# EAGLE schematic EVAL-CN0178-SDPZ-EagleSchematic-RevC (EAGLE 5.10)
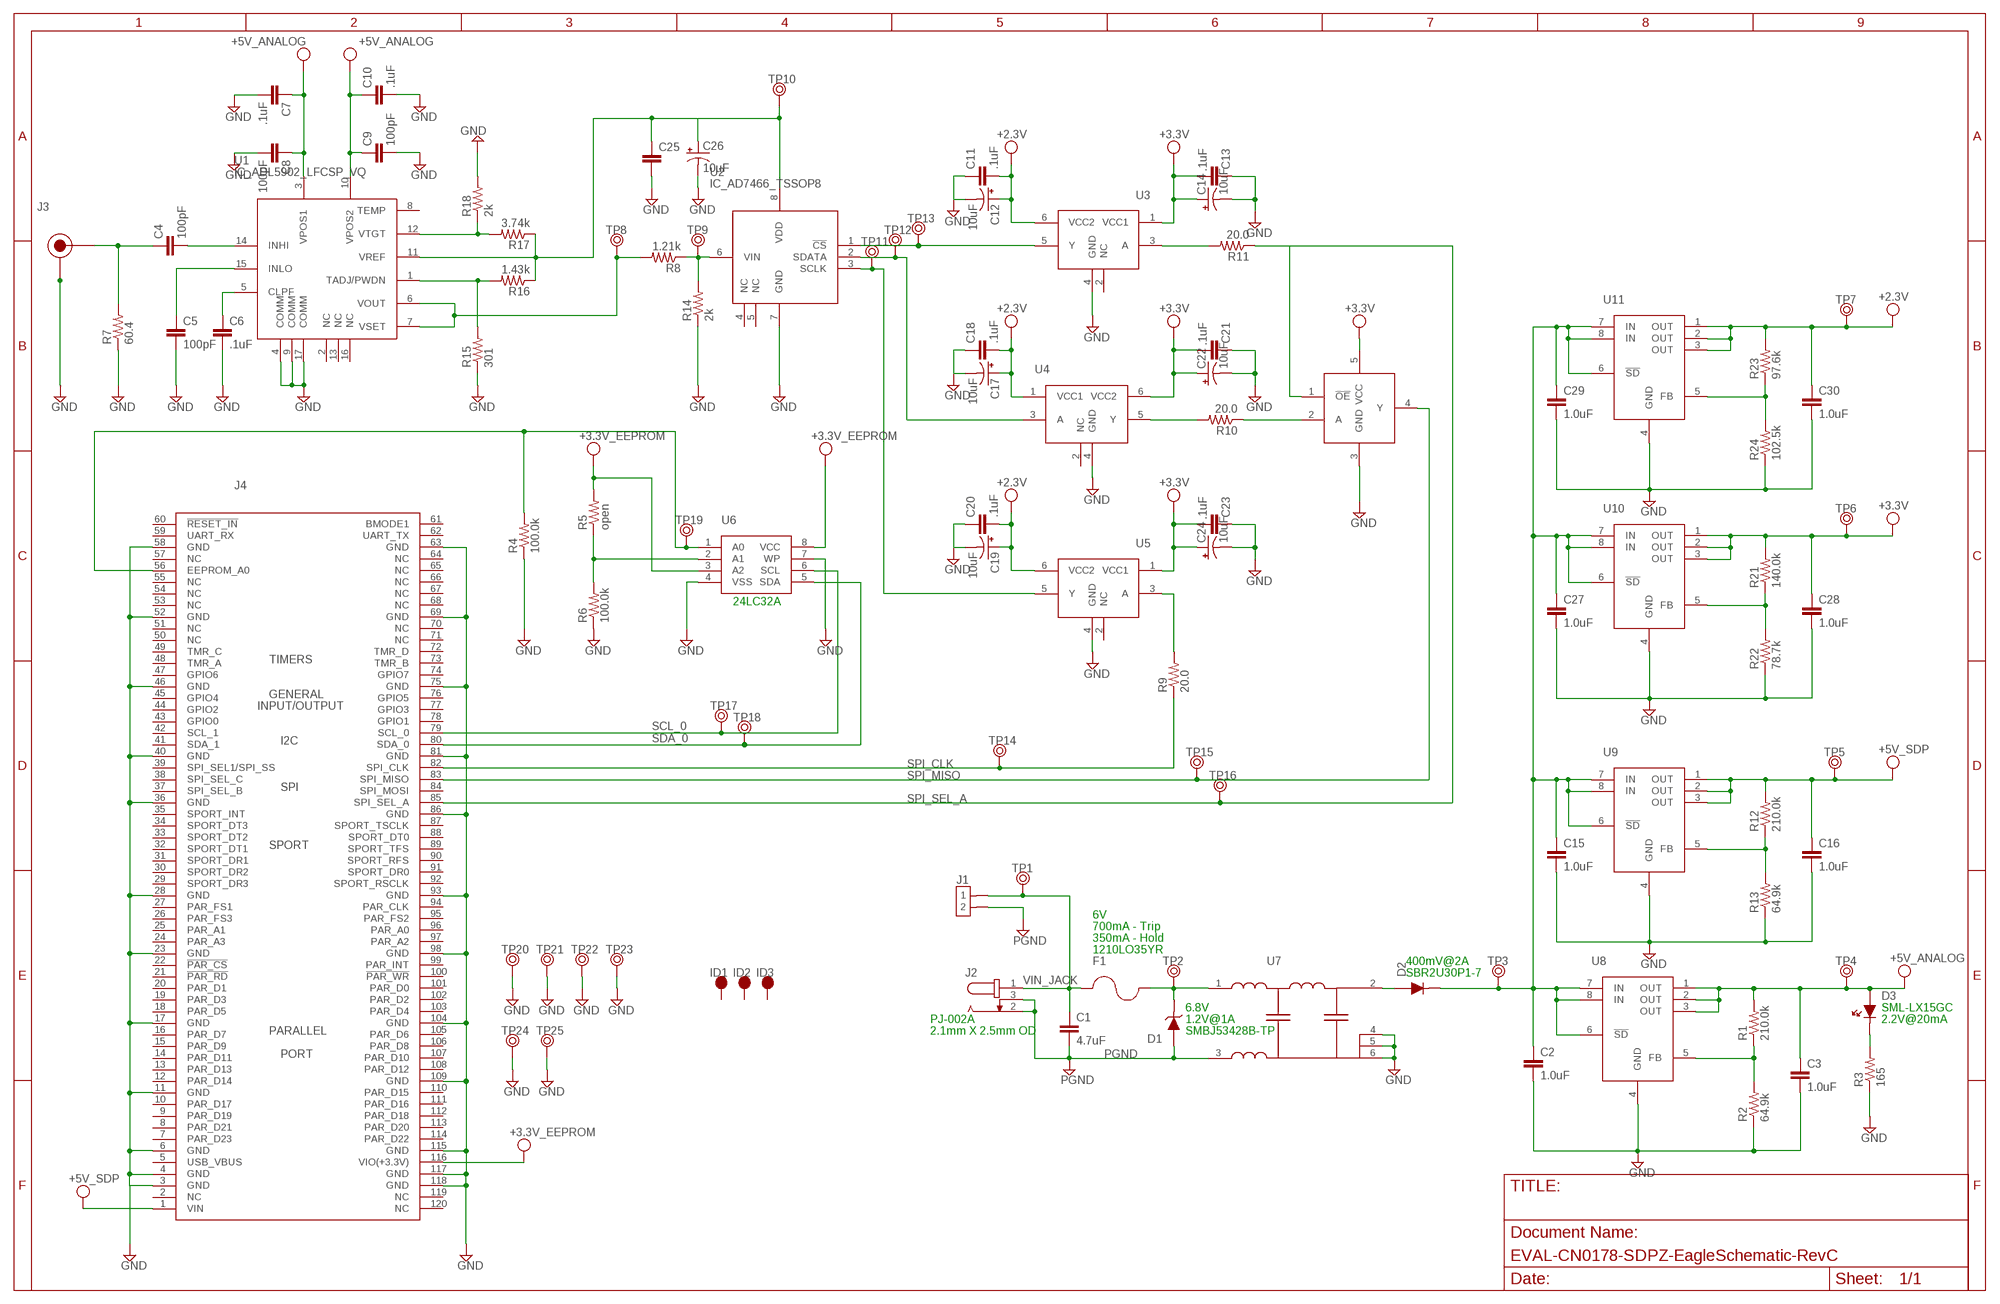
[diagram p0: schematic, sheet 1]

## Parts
C1  4.7uF  CAPACITOR_0603  [C_CAPC1608X55N]
C2  1.0uF  CAPACITOR_0603  [C_CAPC1608X55N]
C3  1.0uF  CAPACITOR_0603  [C_CAPC1608X55N]
C4  100pF  CAPACITOR_0402  [C_CAPC1005X55N]
C5  100pF  CAPACITOR_0402  [C_CAPC1005X55N]
C6  .1uF  CAPACITOR_0402  [C_CAPC1005X55N]
C7  .1uF  CAPACITOR_0402  [C_CAPC1005X55N]
C8  100pF  CAPACITOR_0402  [C_CAPC1005X55N]
C9  100pF  CAPACITOR_0402  [C_CAPC1005X55N]
C10  .1uF  CAPACITOR_0402  [C_CAPC1005X55N]
C11  .1uF  CAPACITOR_0603  [C_CAPC1608X55N]
C12  10uF  CAPACITOR_POL_3216-18  [C_CAPMP3216X180N]
C13  .1uF  CAPACITOR_0603  [C_CAPC1608X55N]
C14  10uF  CAPACITOR_POL_3216-18  [C_CAPMP3216X180N]
C15  1.0uF  CAPACITOR_0603  [C_CAPC1608X55N]
C16  1.0uF  CAPACITOR_0603  [C_CAPC1608X55N]
C17  10uF  CAPACITOR_POL_3216-18  [C_CAPMP3216X180N]
C18  .1uF  CAPACITOR_0603  [C_CAPC1608X55N]
C19  10uF  CAPACITOR_POL_3216-18  [C_CAPMP3216X180N]
C20  .1uF  CAPACITOR_0603  [C_CAPC1608X55N]
C21  .1uF  CAPACITOR_0603  [C_CAPC1608X55N]
C22  10uF  CAPACITOR_POL_3216-18  [C_CAPMP3216X180N]
C23  .1uF  CAPACITOR_0603  [C_CAPC1608X55N]
C24  10uF  CAPACITOR_POL_3216-18  [C_CAPMP3216X180N]
C25  CAPACITOR_0603  [C_CAPC1608X55N]
C26  10uF  CAPACITOR_POL_3216-18  [C_CAPMP3216X180N]
C27  1.0uF  CAPACITOR_0603  [C_CAPC1608X55N]
C28  1.0uF  CAPACITOR_0603  [C_CAPC1608X55N]
C29  1.0uF  CAPACITOR_0603  [C_CAPC1608X55N]
C30  1.0uF  CAPACITOR_0603  [C_CAPC1608X55N]
D1  DIODE_ZENER_DO-214AA,SMB  [D_DIOM5436X241N]
D2  DIODE_RECT_POWERDI-123  [D_POWER123]
D3  DIODE_LED_SOT_23-3  [D_LED_LUMEX_SMD]
F1  FUSE_1210  [C_CAPC3225X94N]
ID1  INDICATOR  [ID_PICKNPLACE]
ID2  INDICATOR  [ID_PICKNPLACE]
ID3  INDICATOR  [ID_PICKNPLACE]
J1  CON_HEADER_2PIN  [CON_HEADER_2PIN]
J2  CON_DC_BARREL_THRU_HOLE  [CON_BARREL_JACK]
J3  CON_COAX_SMD  [CON_COAX_SMD]
J4  CON_SDP_120PIN_SMD  [CON_120PIN_SMD]
R1  210.0k  RESISTOR_0603  [R_RESC1608X50AN]
R2  64.9k  RESISTOR_0603  [R_RESC1608X50AN]
R3  165  RESISTOR_0603  [R_RESC1608X50AN]
R4  100.0k  RESISTOR_0603  [R_RESC1608X50AN]
R5  open  RESISTOR_0603  [R_RESC1608X50AN]
R6  100.0k  RESISTOR_0603  [R_RESC1608X50AN]
R7  60.4  RESISTOR_0402_RF  [R_RESC1005X40N_RF]
R8  1.21k  RESISTOR_0603  [R_RESC1608X50AN]
R9  20.0  RESISTOR_0603  [R_RESC1608X50AN]
R10  20.0  RESISTOR_0603  [R_RESC1608X50AN]
R11  20.0  RESISTOR_0603  [R_RESC1608X50AN]
R12  210.0k  RESISTOR_0603  [R_RESC1608X50AN]
R13  64.9k  RESISTOR_0603  [R_RESC1608X50AN]
R14  2k  RESISTOR_0603  [R_RESC1608X50AN]
R15  301  RESISTOR_0603  [R_RESC1608X50AN]
R16  1.43k  RESISTOR_0603  [R_RESC1608X50AN]
R17  3.74k  RESISTOR_0603  [R_RESC1608X50AN]
R18  2k  RESISTOR_0603  [R_RESC1608X50AN]
R21  140.0k  RESISTOR_0603  [R_RESC1608X50AN]
R22  78.7k  RESISTOR_0603  [R_RESC1608X50AN]
R23  97.6k  RESISTOR_0603  [R_RESC1608X50AN]
R24  102.5k  RESISTOR_0603  [R_RESC1608X50AN]
TP1  TESTPOINT_50MIL  [TP_50MIL]
TP2  TESTPOINT_50MIL  [TP_50MIL]
TP3  TESTPOINT_50MIL  [TP_50MIL]
TP4  TESTPOINT_50MIL  [TP_50MIL]
TP5  TESTPOINT_50MIL  [TP_50MIL]
TP6  TESTPOINT_50MIL  [TP_50MIL]
TP7  TESTPOINT_50MIL  [TP_50MIL]
TP8  TESTPOINT_50MIL  [TP_50MIL]
TP9  TESTPOINT_50MIL  [TP_50MIL]
TP10  TESTPOINT_50MIL  [TP_50MIL]
TP11  TESTPOINT_50MIL  [TP_50MIL]
TP12  TESTPOINT_50MIL  [TP_50MIL]
TP13  TESTPOINT_50MIL  [TP_50MIL]
TP14  TESTPOINT_50MIL  [TP_50MIL]
TP15  TESTPOINT_50MIL  [TP_50MIL]
TP16  TESTPOINT_50MIL  [TP_50MIL]
TP17  TESTPOINT_50MIL  [TP_50MIL]
TP18  TESTPOINT_50MIL  [TP_50MIL]
TP19  TESTPOINT_50MIL  [TP_50MIL]
TP20  TESTPOINT_50MIL  [TP_50MIL]
TP21  TESTPOINT_50MIL  [TP_50MIL]
TP22  TESTPOINT_50MIL  [TP_50MIL]
TP23  TESTPOINT_50MIL  [TP_50MIL]
TP24  TESTPOINT_50MIL  [TP_50MIL]
TP25  TESTPOINT_50MIL  [TP_50MIL]
U1  IC_ADL5902_LFCSP_VQ  [IC_QFN65P400X400X100-17VN]
U2  IC_AD7466_TSSOP8  [IC_SOP65P490X94-8N]
U3  IC_ADG3231_SOT-23  [IC_SOT95P280X145-6AN]
U4  IC_ADG3231_SOT-23  [IC_SOT95P280X145-6AN]
U5  IC_ADG3231_SOT-23  [IC_SOT95P280X145-6AN]
U6  IC_24LC32A_SOIC8  [IC_SOIC127P600X175-8N]
U7  IC_BNX016-01  [IC_BNX016-01]
U8  IC_ADP3336_TSSOP8  [IC_SOP65P490X94-8N]
U9  IC_ADP3336_TSSOP8  [IC_SOP65P490X94-8N]
U10  IC_ADP3336_TSSOP8  [IC_SOP65P490X94-8N]
U11  IC_ADP3336_TSSOP8  [IC_SOP65P490X94-8N]
U12  IC_74HC_HCT1G125  [IC_SOT65P210X110-5N]

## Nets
+2.3V: C11.2 C12.1(+) C17.1(+) C18.2 C19.1(+) C20.2 C30.1 R23.2 TP7.1 U3.6(VCC2) U4.1(VCC1) U5.6(VCC2) U11.1(OUT) U11.2(OUT) U11.3(OUT)
+3.3V: C13.2 C14.1(+) C21.2 C22.1(+) C23.2 C24.1(+) C28.1 R21.2 TP6.1 U3.1(VCC1) U4.6(VCC2) U5.1(VCC1) U10.1(OUT) U10.2(OUT) U10.3(OUT) U12.5(VCC)
+3.3V_EEPROM: J4.116(VIO(+3.3V)) R5.2 U6.3(A2) U6.8(VCC)
+5V_ANALOG: C3.1 C7.1 C8.1 C9.1 C10.1 D3.2(A) R1.2 TP4.1 U1.3(VPOS1) U1.10(VPOS2) U8.1(OUT) U8.2(OUT) U8.3(OUT)
+5V_SDP: C16.1 J4.1(VIN) R12.2 TP5.1 U9.1(OUT) U9.2(OUT) U9.3(OUT)
GND: C2.2 C3.2 C5.2 C6.2 C7.2 C8.2 C9.2 C10.2 C11.1 C12.2(-) C13.1 C14.2(-) C15.2 C16.2 C17.2(-) C18.1 C19.2(-) C20.1 C21.1 C22.2(-) C23.1 C24.2(-) C25.2 C26.2(-) C27.2 C28.2 C29.2 C30.2 J3.PAD1(SHD) J3.PAD2(SHD) J3.PAD3(SHD) J3.PAD4(SHD) J4.3(GND) J4.4(GND) J4.6(GND) J4.11(GND) J4.17(GND) J4.23(GND) J4.28(GND) J4.36(GND) J4.40(GND) J4.46(GND) J4.52(GND) J4.58(GND) J4.63(GND) J4.69(GND) J4.75(GND) J4.81(GND) J4.86(GND) J4.93(GND) J4.98(GND) J4.104(GND) J4.109(GND) J4.115(GND) J4.117(GND) J4.118(GND) R2.1 R3.1 R4.1 R6.1 R7.1 R13.1 R14.1 R15.1 R18.2 R22.1 R24.1 TP20.1 TP21.1 TP22.1 TP23.1 TP24.1 TP25.1 U1.4(COMM) U1.9(COMM) U1.17(COMM) U2.7(GND) U3.4(GND) U4.4(GND) U5.4(GND) U6.4(VSS) U6.7(WP) U7.4(CG) U7.5(CG) U7.6(CG) U8.4(GND) U9.4(GND) U10.4(GND) U11.4(GND) U12.3(GND)
N$1: C6.1 U1.5(CLPF)
N$2: C5.1 U1.15(INLO)
N$3: C4.2 U1.14(INHI)
N$4: R17.2 R18.1 U1.12(VTGT)
N$5: C4.1 J3.SIG R7.2
N$6: J4.56(EEPROM_A0) R4.2 TP19.1 U6.1(A0)
N$7: TP13.1 U2.1(!CS) U3.5(Y)
N$8: R15.2 R16.2 U1.1(TADJ/PWDN)
N$9: R5.1 R6.2 U6.2(A1)
N$10: R8.1 R14.2 TP9.1 U2.6(VIN)
N$11: R8.2 TP8.1 U1.6(VOUT) U1.7(VSET)
N$12: R10.1 U12.2(A)
N$13: TP12.1 U2.2(SDATA) U4.3(A)
N$14: R1.1 R2.2 U8.5(FB)
N$15: D1.K F1.2 TP2.1 U7.1(B)
N$16: D2.A U7.2(CB)
N$17: TP11.1 U2.3(SCLK) U5.5(Y)
N$18: D3.3(K) R3.2
N$19: R12.1 R13.2 U9.5(FB)
N$20: R9.2 U5.3(A)
N$21: R21.1 R22.2 U10.5(FB)
N$22: R23.1 R24.2 U11.5(FB)
N$23: R10.2 U4.5(Y)
N$24: R11.2 U3.3(A)
N$27: C25.1 C26.1(+) R16.1 R17.1 TP10.1 U1.11(VREF) U2.8(VDD)
PGND: C1.2 D1.A J1.2 J2.2 J2.3 U7.3(PSG)
SCL_0: J4.79(SCL_0) TP17.1 U6.6(SCL)
SDA_0: J4.80(SDA_0) TP18.1 U6.5(SDA)
SPI_CLK: J4.82(SPI_CLK) R9.1 TP14.1
SPI_MISO: J4.83(SPI_MISO) TP15.1 U12.4(Y)
SPI_SEL_A: J4.85(SPI_SEL_A) R11.1 TP16.1 U12.1(!OE)
VIN2: C2.1 C15.1 C27.1 C29.1 D2.K TP3.1 U8.6(!SD) U8.7(IN) U8.8(IN) U9.6(!SD) U9.7(IN) U9.8(IN) U10.6(!SD) U10.7(IN) U10.8(IN) U11.6(!SD) U11.7(IN) U11.8(IN)
VIN_JACK: C1.1 F1.1 J1.1 J2.1 TP1.1
Unconnected: ID1.P$1 ID2.P$1 ID3.P$1 J4.2(NC) J4.5(USB_VBUS) J4.7(PAR_D23) J4.8(PAR_D21) J4.9(PAR_D19) J4.10(PAR_D17) J4.12(PAR_D14) J4.13(PAR_D13) J4.14(PAR_D11) J4.15(PAR_D9) J4.16(PAR_D7) J4.18(PAR_D5) J4.19(PAR_D3) J4.20(PAR_D1) J4.21(!PAR_RD) J4.22(!PAR_CS) J4.24(PAR_A3) J4.25(PAR_A1) J4.26(PAR_FS3) J4.27(PAR_FS1) J4.29(SPORT_DR3) J4.30(SPORT_DR2) J4.31(SPORT_DR1) J4.32(SPORT_DT1) J4.33(SPORT_DT2) J4.34(SPORT_DT3) J4.35(SPORT_INT) J4.37(SPI_SEL_B) J4.38(SPI_SEL_C) J4.39(SPI_SEL1/SPI_SS) J4.41(SDA_1) J4.42(SCL_1) J4.43(GPIO0) J4.44(GPIO2) J4.45(GPIO4) J4.47(GPIO6) J4.48(TMR_A) J4.49(TMR_C) J4.50(NC) J4.51(NC) J4.53(NC) J4.54(NC) J4.55(NC) J4.57(NC) J4.59(UART_RX) J4.60(!RESET_IN) J4.61(BMODE1) J4.62(UART_TX) J4.64(NC) J4.65(NC) J4.66(NC) J4.67(NC) J4.68(NC) J4.70(NC) J4.71(NC) J4.72(TMR_D) J4.73(TMR_B) J4.74(GPIO7) J4.76(GPIO5) J4.77(GPIO3) J4.78(GPIO1) J4.84(SPI_MOSI) J4.87(SPORT_TSCLK) J4.88(SPORT_DT0) J4.89(SPORT_TFS) J4.90(SPORT_RFS) J4.91(SPORT_DR0) J4.92(SPORT_RSCLK) J4.94(PAR_CLK) J4.95(PAR_FS2) J4.96(PAR_A0) J4.97(PAR_A2) J4.99(PAR_INT) J4.100(!PAR_WR) J4.101(PAR_D0) J4.102(PAR_D2) J4.103(PAR_D4) J4.105(PAR_D6) J4.106(PAR_D8) J4.107(PAR_D10) J4.108(PAR_D12) J4.110(PAR_D15) J4.111(PAR_D16) J4.112(PAR_D18) J4.113(PAR_D20) J4.114(PAR_D22) J4.119(NC) J4.120(NC) U1.2(NC) U1.8(TEMP) U1.13(NC) U1.16(NC) U2.4(NC) U2.5(NC) U3.2(NC) U4.2(NC) U5.2(NC)

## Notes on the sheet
- 24LC32A
- 6V
- 700mA - Trip
- 350mA - Hold
- 1210LO35YR
- 400mV@2A
- SBR2U30P1-7
- 6.8V | SML-LX15GC
- PJ-002A | 1.2V@1A | 2.2V@20mA
- 2.1mm X 2.5mm OD | SMBJ53428B-TP

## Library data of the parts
C1-C11 C13 C15 C16 C18 C20 C21 C23 C25 C27-C30 = CN-0178-RevC:CAPACITOR: Capacitor, Non-Polarized
C12 C14 C17 C19 C22 C24 = CN-0178-RevC:CAPACITOR_POL: Capacitor, Polarized
C26 = CN-0178-RevB:CAPACITOR_POL: Capacitor, Polarized
D1 = CN-0178-RevC:DIODE_ZENER: Diode, Zener
D2 = CN-0178-RevC:DIODE_RECT: Diode, Rectifier
D3 = CN-0178-RevC:DIODE_LED: LED
F1 = CN-0178-RevC:FUSE: Fuse
ID1-ID3 = CN0150:INDICATOR
J1 = CN-0178-RevC:CON_HEADER_2PIN
J2 = CN-0178-RevC:CON_DC_BARREL: DC Barrel Jack
J3 = CN-0178-RevC:CON_COAX: Coaxial Connector
J4 = CN-0178-RevC:CON_SDP: SDP Connector
R1-R18 R21-R24 = CN-0178-RevC:RESISTOR: Resistor
TP1-TP25 = CN-0178-RevC:TESTPOINT: Testpoint
U1 = CN-0178-RevC:IC_ADL5902: 50MHz to 9GHz, 65 dB TruPower Detector.
U2 = CN-0178-RevC:IC_AD7466: 1.6V -3.6V Micropower, successive approximation, 200kSPS 12-Bit ADC.
U3-U5 = CN-0178-RevC:IC_ADG3231: 1.65V to 3.6V single channel, bi-directional level translator with uni-directional signal path.
U6 = CN-0178-RevC:IC_24LC32A: Microchip 32K I2C Serial EEPROM; P/N 24LC32A-I/SN
U7 = CN-0178-RevC:IC_BNX016-01: Murata Noise Suppression Filter; P/N BNX016
U8-U11 = CN-0178-RevC:IC_ADP3336: Small, Adjustable Output, 500 mA anyCAP® Low Dropout Regulator
U12 = CN-0178-RevC:IC_74HC_HCT1G125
